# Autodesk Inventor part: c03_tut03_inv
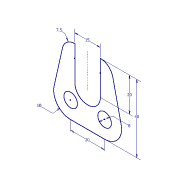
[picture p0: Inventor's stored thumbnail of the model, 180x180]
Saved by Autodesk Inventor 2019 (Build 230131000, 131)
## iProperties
Created: 2017-04
Part Number: c03_tut03_inv
Material: Generic
Document SubType Name: Modeling
Designer: CADCIM 00
Density: 1 g/cm^3
Appearance: Default
Author: CADCIM 00
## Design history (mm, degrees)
sketch "Sketch1"
  geometry: L1 (-10, -20)-(10, -20); L2 (19.756, -7.805)-(14.817, 14.146); L3 (7.5, 20)-(7.5, 0); L4 (-7.5, 0)-(-7.5, 20); L5 (-14.817, 14.146)-(-19.756, -7.805); L6 (0, 0)-(0, 20); C1 r 4 at (-10, -10); C2 r 4 at (10, -10); A1 r 10 centre (10, -10) between (10, -20) and (19.756, -7.805); A2 r 7.5 centre (7.5, 12.5) between (14.817, 14.146) and (7.5, 20); A3 r 7.5 centre (0, 0) between (-7.5, 0) and (7.5, 0); A4 r 7.5 centre (-7.5, 12.5) between (-7.5, 20) and (-14.817, 14.146); A5 r 10 centre (-10, -10) between (-19.756, -7.805) and (-10, -20); 1 further point
  constraints: 12 end point, 10 point on circle, 8 tangent, 7 centre point, 3 coincident, 3 equal radius, 2 equal length, 2 point on line, 1 horizontal, 1 horizontal alignment, 1 parallel, 1 perpendicular, 1 vertical, 3 other
  dimensions: "d0" = 20 distance of L1.start L1.end; "d1" = 7.5 radius of A2; "d2" = 10 radius of A1; "d3" = 15 distance between parallel lines of L4 L3; "d5" = 40 distance from line of L1 L4.end; "d6" = 20 distance of L4.start L4.end; "d7" = 8 diameter of C1
